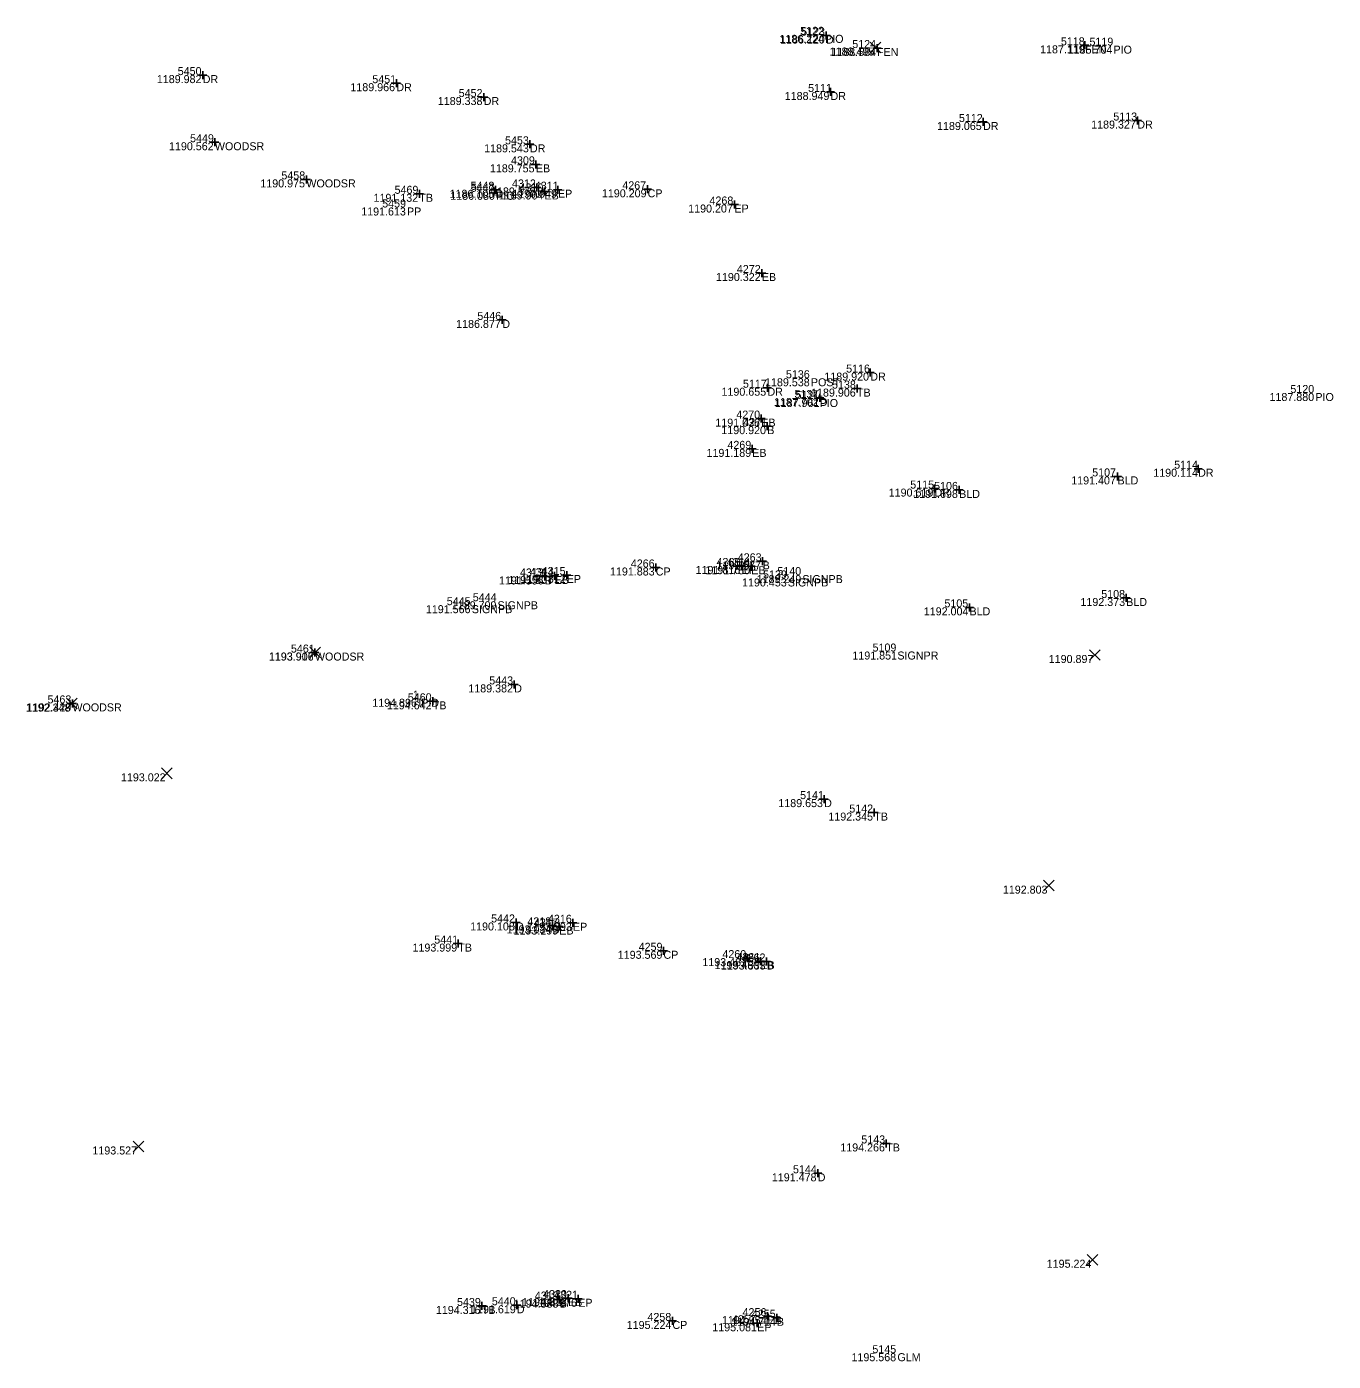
# Model space of a CAD drawing. Extents: x 2044997 to 2050342, y 455233 to 458054.
# Drawn here: x 2047538.1 to 2047701.3, y 457708.4 to 457875.1 of the extents above; entities that cross this region are included whole.
import ezdxf

# ---------------------------------------------------------------- set-up
doc = ezdxf.new("R2010")
doc.units = 0
for name, color, linetype in [('SV_X_Random_Point', 7, 'Continuous'), ('SV_X_Shot_Marker', 7, 'Continuous'), ('SV_X_Text_Comment', 7, 'Continuous'), ('SV_X_Text_Elevation', 7, 'Continuous'), ('SV_X_Text_Name', 7, 'Continuous')]:
    doc.layers.add(name, color=color, linetype=linetype)

msp = doc.modelspace()

# ---------------------------------------------------------------- linework, layer by layer
at = {"layer": 'SV_X_Random_Point'}
for p, q in [((2047643.48, 457871.84), (2047644.81, 457873.17)), ((2047643.48, 457873.17), (2047644.81, 457871.84)), ((2047573.45, 457796.27), (2047574.79, 457797.6)), ((2047573.45, 457797.6), (2047574.79, 457796.27)), ((2047670.88, 457795.95), (2047672.21, 457797.28)), ((2047670.88, 457797.28), (2047672.21, 457795.95)), ((2047543.06, 457789.89), (2047544.39, 457791.22)), ((2047543.06, 457791.22), (2047544.39, 457789.89)), ((2047554.93, 457781.16), (2047556.27, 457782.5)), ((2047554.93, 457782.5), (2047556.27, 457781.16)), ((2047665.1, 457767.13), (2047666.43, 457768.47)), ((2047665.1, 457768.47), (2047666.43, 457767.13)), ((2047551.41, 457734.54), (2047552.74, 457735.87)), ((2047551.41, 457735.87), (2047552.74, 457734.54)), ((2047670.56, 457720.39), (2047671.89, 457721.72)), ((2047670.56, 457721.72), (2047671.89, 457720.39))]:
    msp.add_line(p, q, dxfattribs=at)
at = {"layer": 'SV_X_Shot_Marker'}
for p, q in [((2047637.45, 457874.01), (2047638.45, 457874.01)), ((2047637.95, 457874.51), (2047637.95, 457873.51)), ((2047637.95, 457874.01), (2047637.95, 457874.01)), ((2047643.82, 457872.45), (2047644.82, 457872.45)), ((2047644.32, 457872.95), (2047644.32, 457871.95)), ((2047644.32, 457872.45), (2047644.32, 457872.45)), ((2047669.8, 457872.79), (2047670.8, 457872.79)), ((2047670.3, 457873.29), (2047670.3, 457872.29)), ((2047670.3, 457872.79), (2047670.3, 457872.79)), ((2047559.58, 457869.07), (2047560.58, 457869.07)), ((2047560.08, 457869.57), (2047560.08, 457868.57)), ((2047560.08, 457869.07), (2047560.08, 457869.07)), ((2047584.27, 457868.56), (2047584.27, 457867.56)), ((2047583.77, 457868.06), (2047584.77, 457868.06)), ((2047584.27, 457868.06), (2047584.27, 457868.06)), ((2047595.18, 457866.83), (2047595.18, 457865.83)), ((2047638.01, 457866.96), (2047639.01, 457866.96)), ((2047638.51, 457867.46), (2047638.51, 457866.46)), ((2047638.51, 457866.96), (2047638.51, 457866.96)), ((2047594.68, 457866.33), (2047595.68, 457866.33)), ((2047595.18, 457866.33), (2047595.18, 457866.33)), ((2047657.56, 457863.71), (2047657.56, 457862.71)), ((2047676.34, 457863.39), (2047677.34, 457863.39)), ((2047676.84, 457863.89), (2047676.84, 457862.89)), ((2047676.84, 457863.39), (2047676.84, 457863.39)), ((2047657.06, 457863.21), (2047658.06, 457863.21)), ((2047657.56, 457863.21), (2047657.56, 457863.21)), ((2047561.1, 457860.68), (2047562.1, 457860.68)), ((2047561.6, 457861.18), (2047561.6, 457860.18)), ((2047561.6, 457860.68), (2047561.6, 457860.68)), ((2047600.46, 457860.42), (2047601.46, 457860.42)), ((2047600.96, 457860.92), (2047600.96, 457859.92)), ((2047600.96, 457860.42), (2047600.96, 457860.42)), ((2047601.7, 457858.42), (2047601.7, 457857.42)), ((2047601.2, 457857.92), (2047602.2, 457857.92)), ((2047601.7, 457857.92), (2047601.7, 457857.92)), ((2047572.53, 457856.04), (2047573.53, 457856.04)), ((2047573.03, 457856.54), (2047573.03, 457855.54)), ((2047573.03, 457856.04), (2047573.03, 457856.04)), ((2047596.66, 457855.24), (2047596.66, 457854.24)), ((2047601.34, 457855.03), (2047602.34, 457855.03)), ((2047601.84, 457855.53), (2047601.84, 457854.53)), ((2047601.84, 457855.03), (2047601.84, 457855.03)), ((2047602.78, 457855.03), (2047602.78, 457854.03)), ((2047604.46, 457855.25), (2047604.46, 457854.25)), ((2047615.66, 457855.3), (2047615.66, 457854.3)), ((2047586.65, 457854.24), (2047587.65, 457854.24)), ((2047587.15, 457854.74), (2047587.15, 457853.74)), ((2047587.15, 457854.24), (2047587.15, 457854.24)), ((2047596.16, 457854.74), (2047597.16, 457854.74)), ((2047596.66, 457854.74), (2047596.66, 457854.74)), ((2047602.28, 457854.53), (2047603.28, 457854.53)), ((2047602.78, 457854.53), (2047602.78, 457854.53)), ((2047603.96, 457854.75), (2047604.96, 457854.75)), ((2047604.46, 457854.75), (2047604.46, 457854.75)), ((2047615.16, 457854.8), (2047616.16, 457854.8)), ((2047615.66, 457854.8), (2047615.66, 457854.8)), ((2047626.51, 457853.4), (2047626.51, 457852.4)), ((2047626.01, 457852.9), (2047627.01, 457852.9)), ((2047626.51, 457852.9), (2047626.51, 457852.9)), ((2047629.43, 457844.34), (2047630.43, 457844.34)), ((2047629.93, 457844.84), (2047629.93, 457843.84)), ((2047629.93, 457844.34), (2047629.93, 457844.34)), ((2047597.01, 457838.48), (2047598.01, 457838.48)), ((2047597.51, 457838.98), (2047597.51, 457837.98)), ((2047597.51, 457838.48), (2047597.51, 457838.48)), ((2047642.98, 457831.9), (2047643.98, 457831.9)), ((2047643.48, 457832.4), (2047643.48, 457831.4)), ((2047643.48, 457831.9), (2047643.48, 457831.9)), ((2047630.13, 457830.01), (2047631.13, 457830.01)), ((2047630.63, 457830.51), (2047630.63, 457829.51)), ((2047630.63, 457830.01), (2047630.63, 457830.01)), ((2047641.82, 457830.4), (2047641.82, 457829.4)), ((2047636.67, 457828.73), (2047637.67, 457828.73)), ((2047637.17, 457829.23), (2047637.17, 457828.23)), ((2047637.17, 457828.73), (2047637.17, 457828.73)), ((2047641.32, 457829.9), (2047642.32, 457829.9)), ((2047641.82, 457829.9), (2047641.82, 457829.9)), ((2047629.86, 457826.65), (2047629.86, 457825.65)), ((2047629.36, 457826.15), (2047630.36, 457826.15)), ((2047629.86, 457826.15), (2047629.86, 457826.15)), ((2047630.11, 457825.21), (2047631.11, 457825.21)), ((2047630.61, 457825.71), (2047630.61, 457824.71)), ((2047630.61, 457825.21), (2047630.61, 457825.21)), ((2047628.23, 457822.37), (2047629.23, 457822.37)), ((2047628.73, 457822.87), (2047628.73, 457821.87)), ((2047628.73, 457822.37), (2047628.73, 457822.37)), ((2047684.43, 457820.39), (2047684.43, 457819.39)), ((2047673.86, 457818.93), (2047674.86, 457818.93)), ((2047674.36, 457819.43), (2047674.36, 457818.43)), ((2047674.36, 457818.93), (2047674.36, 457818.93)), ((2047683.93, 457819.89), (2047684.93, 457819.89)), ((2047684.43, 457819.89), (2047684.43, 457819.89)), ((2047650.99, 457817.41), (2047651.99, 457817.41)), ((2047651.49, 457817.91), (2047651.49, 457816.91)), ((2047651.49, 457817.41), (2047651.49, 457817.41)), ((2047654.08, 457817.24), (2047655.08, 457817.24)), ((2047654.58, 457817.74), (2047654.58, 457816.74)), ((2047654.58, 457817.24), (2047654.58, 457817.24)), ((2047629.53, 457808.32), (2047630.53, 457808.32)), ((2047630.03, 457808.82), (2047630.03, 457807.82)), ((2047630.03, 457808.32), (2047630.03, 457808.32)), ((2047602.82, 457806.93), (2047602.82, 457805.93)), ((2047604.04, 457806.99), (2047604.04, 457805.99)), ((2047605.56, 457807.11), (2047605.56, 457806.11)), ((2047616.18, 457807.55), (2047617.18, 457807.55)), ((2047616.68, 457808.05), (2047616.68, 457807.05)), ((2047616.68, 457807.55), (2047616.68, 457807.55)), ((2047626.9, 457807.74), (2047627.9, 457807.74)), ((2047627.4, 457808.24), (2047627.4, 457807.24)), ((2047627.4, 457807.74), (2047627.4, 457807.74)), ((2047628.11, 457807.71), (2047629.11, 457807.71)), ((2047628.61, 457808.21), (2047628.61, 457807.21)), ((2047628.61, 457807.71), (2047628.61, 457807.71)), ((2047602.32, 457806.43), (2047603.32, 457806.43)), ((2047602.82, 457806.43), (2047602.82, 457806.43)), ((2047603.54, 457806.49), (2047604.54, 457806.49)), ((2047604.04, 457806.49), (2047604.04, 457806.49)), ((2047605.06, 457806.61), (2047606.06, 457806.61)), ((2047605.56, 457806.61), (2047605.56, 457806.61)), ((2047674.95, 457803.74), (2047675.95, 457803.74)), ((2047675.45, 457804.24), (2047675.45, 457803.24)), ((2047675.45, 457803.74), (2047675.45, 457803.74)), ((2047655.37, 457802.57), (2047656.37, 457802.57)), ((2047655.87, 457803.07), (2047655.87, 457802.07)), ((2047655.87, 457802.57), (2047655.87, 457802.57)), ((2047573.6, 457796.92), (2047574.6, 457796.92)), ((2047574.1, 457797.42), (2047574.1, 457796.42)), ((2047574.1, 457796.92), (2047574.1, 457796.92)), ((2047598.99, 457793.44), (2047598.99, 457792.44)), ((2047598.49, 457792.94), (2047599.49, 457792.94)), ((2047598.99, 457792.94), (2047598.99, 457792.94)), ((2047543.3, 457790.57), (2047544.3, 457790.57)), ((2047543.8, 457791.07), (2047543.8, 457790.07)), ((2047543.8, 457790.57), (2047543.8, 457790.57)), ((2047588.32, 457790.83), (2047589.32, 457790.83)), ((2047588.82, 457791.33), (2047588.82, 457790.33)), ((2047588.82, 457790.83), (2047588.82, 457790.83)), ((2047637.21, 457778.61), (2047638.21, 457778.61)), ((2047637.71, 457779.11), (2047637.71, 457778.11)), ((2047637.71, 457778.61), (2047637.71, 457778.61)), ((2047643.48, 457776.93), (2047644.48, 457776.93)), ((2047643.98, 457777.43), (2047643.98, 457776.43)), ((2047643.98, 457776.93), (2047643.98, 457776.93)), ((2047599.22, 457763.7), (2047599.22, 457762.7)), ((2047603.76, 457763.33), (2047603.76, 457762.33)), ((2047606.33, 457763.66), (2047606.33, 457762.66)), ((2047598.72, 457763.2), (2047599.72, 457763.2)), ((2047599.22, 457763.2), (2047599.22, 457763.2)), ((2047603.26, 457762.83), (2047604.26, 457762.83)), ((2047603.76, 457762.83), (2047603.76, 457762.83)), ((2047604.12, 457762.69), (2047605.12, 457762.69)), ((2047604.62, 457763.19), (2047604.62, 457762.19)), ((2047604.62, 457762.69), (2047604.62, 457762.69)), ((2047605.83, 457763.16), (2047606.83, 457763.16)), ((2047606.33, 457763.16), (2047606.33, 457763.16)), ((2047591.51, 457760.56), (2047592.51, 457760.56)), ((2047592.01, 457761.06), (2047592.01, 457760.06)), ((2047592.01, 457760.56), (2047592.01, 457760.56)), ((2047617.64, 457760.16), (2047617.64, 457759.16)), ((2047617.14, 457759.66), (2047618.14, 457759.66)), ((2047617.64, 457759.66), (2047617.64, 457759.66)), ((2047627.62, 457758.74), (2047628.62, 457758.74)), ((2047628.12, 457759.24), (2047628.12, 457758.24)), ((2047628.12, 457758.74), (2047628.12, 457758.74)), ((2047629.25, 457758.37), (2047630.25, 457758.37)), ((2047629.75, 457758.87), (2047629.75, 457757.87)), ((2047629.75, 457758.37), (2047629.75, 457758.37)), ((2047630.03, 457758.32), (2047631.03, 457758.32)), ((2047630.53, 457758.82), (2047630.53, 457757.82)), ((2047630.53, 457758.32), (2047630.53, 457758.32)), ((2047644.97, 457735.59), (2047645.97, 457735.59)), ((2047645.47, 457736.09), (2047645.47, 457735.09)), ((2047645.47, 457735.59), (2047645.47, 457735.59)), ((2047636.41, 457731.86), (2047637.41, 457731.86)), ((2047636.91, 457732.36), (2047636.91, 457731.36)), ((2047636.91, 457731.86), (2047636.91, 457731.86)), ((2047604.67, 457716.58), (2047604.67, 457715.58)), ((2047605.72, 457716.77), (2047605.72, 457715.77)), ((2047606.99, 457716.68), (2047606.99, 457715.68)), ((2047594.45, 457715.28), (2047595.45, 457715.28)), ((2047594.95, 457715.78), (2047594.95, 457714.78)), ((2047594.95, 457715.28), (2047594.95, 457715.28)), ((2047598.82, 457715.37), (2047599.82, 457715.37)), ((2047599.32, 457715.87), (2047599.32, 457714.87)), ((2047599.32, 457715.37), (2047599.32, 457715.37)), ((2047604.17, 457716.08), (2047605.17, 457716.08)), ((2047604.67, 457716.08), (2047604.67, 457716.08)), ((2047605.22, 457716.27), (2047606.22, 457716.27)), ((2047605.72, 457716.27), (2047605.72, 457716.27)), ((2047606.49, 457716.18), (2047607.49, 457716.18)), ((2047606.99, 457716.18), (2047606.99, 457716.18)), ((2047618.26, 457713.41), (2047619.26, 457713.41)), ((2047618.76, 457713.91), (2047618.76, 457712.91)), ((2047618.76, 457713.41), (2047618.76, 457713.41)), ((2047629.35, 457713.62), (2047629.35, 457712.62)), ((2047630.15, 457714.01), (2047631.15, 457714.01)), ((2047630.65, 457714.51), (2047630.65, 457713.51)), ((2047630.65, 457714.01), (2047630.65, 457714.01)), ((2047631.31, 457713.81), (2047632.31, 457713.81)), ((2047631.81, 457714.31), (2047631.81, 457713.31)), ((2047631.81, 457713.81), (2047631.81, 457713.81)), ((2047628.85, 457713.12), (2047629.85, 457713.12)), ((2047629.35, 457713.12), (2047629.35, 457713.12))]:
    msp.add_line(p, q, dxfattribs=at)

# ---------------------------------------------------------------- texts
at = {"layer": 'SV_X_Text_Comment'}
for s, p in [('PIO', (2047637.83, 457873.1)), ('D', (2047637.95, 457873.01)), ('FEN', (2047644.32, 457871.45)), ('FEN', (2047670.3, 457871.79)), ('PIO', (2047673.86, 457871.75)), ('DR', (2047560.08, 457868.07)), ('DR', (2047584.27, 457867.06)), ('DR', (2047638.51, 457865.96)), ('DR', (2047595.18, 457865.33)), ('DR', (2047676.84, 457862.39)), ('DR', (2047657.56, 457862.21)), ('WOODSR', (2047561.6, 457859.68)), ('DR', (2047600.96, 457859.42)), ('EB', (2047601.7, 457856.92)), ('WOODSR', (2047573.03, 457855.04)), ('B', (2047601.84, 457854.03)), ('TB', (2047587.15, 457853.24)), ('D', (2047596.66, 457853.74)), ('PIO', (2047596.73, 457853.49)), ('EB', (2047602.78, 457853.53)), ('EP', (2047604.46, 457853.75)), ('CP', (2047615.66, 457853.8)), ('PP', (2047585.6, 457851.53)), ('EP', (2047626.51, 457851.9)), ('EB', (2047629.93, 457843.34)), ('D', (2047597.51, 457837.48)), ('DR', (2047643.48, 457830.9)), ('DR', (2047630.63, 457829.01)), ('POST', (2047636.06, 457830.19)), ('PIO', (2047637.15, 457827.6)), ('D', (2047637.17, 457827.73)), ('TB', (2047641.82, 457828.9)), ('PIO', (2047699.08, 457828.35)), ('EB', (2047629.86, 457825.15)), ('B', (2047630.61, 457824.21)), ('EB', (2047628.73, 457821.37)), ('BLD', (2047674.36, 457817.93)), ('DR', (2047684.43, 457818.89)), ('DR', (2047651.49, 457816.41)), ('BLD', (2047654.58, 457816.24)), ('B', (2047630.03, 457807.32)), ('CP', (2047616.68, 457806.55)), ('EP', (2047627.4, 457806.74)), ('EB', (2047628.61, 457806.71)), ('SIGNPB', (2047634.99, 457805.6)), ('B', (2047602.82, 457805.43)), ('EB', (2047604.04, 457805.49)), ('EP', (2047605.56, 457805.61)), ('SIGNPB', (2047633.18, 457805.18)), ('SIGNPB', (2047596.91, 457802.33)), ('BLD', (2047675.45, 457802.74)), ('SIGNPB', (2047593.7, 457801.84)), ('BLD', (2047655.87, 457801.57)), ('WOODSR', (2047574.1, 457795.92)), ('SIGNPR', (2047646.86, 457796.05)), ('D', (2047598.99, 457791.94)), ('WOODSR', (2047543.8, 457789.57)), ('IPID', (2047587, 457790.15)), ('TB', (2047588.82, 457789.83)), ('D', (2047637.71, 457777.61)), ('TB', (2047643.98, 457775.93)), ('D', (2047599.22, 457762.2)), ('B', (2047603.76, 457761.83)), ('EB', (2047604.62, 457761.69)), ('EP', (2047606.33, 457762.16)), ('TB', (2047592.01, 457759.56)), ('CP', (2047617.64, 457758.66)), ('EP', (2047628.12, 457757.74)), ('EB', (2047629.75, 457757.37)), ('B', (2047630.53, 457757.32)), ('TB', (2047645.47, 457734.59)), ('D', (2047636.91, 457730.86)), ('TB', (2047594.95, 457714.28)), ('D', (2047599.32, 457714.37)), ('B', (2047604.67, 457715.08)), ('EB', (2047605.72, 457715.27)), ('EP', (2047606.99, 457715.18)), ('CP', (2047618.76, 457712.41)), ('EB', (2047630.65, 457713.01)), ('B', (2047631.81, 457712.81)), ('EP', (2047629.35, 457712.12)), ('GLM', (2047646.87, 457708.38))]:
    msp.add_text(s, height=1, dxfattribs=at).set_placement(p)
at = {"layer": 'SV_X_Text_Elevation'}
for s, p in [('1186.224', (2047632.13, 457873.1)), ('1186.120', (2047632.21, 457873.01)), ('1188.495', (2047638.4, 457871.51)), ('1188.584', (2047638.61, 457871.45)), ('1187.119', (2047664.69, 457871.79)), ('1185.704', (2047668.15, 457871.75)), ('1189.982', (2047554.35, 457868.07)), ('1189.966', (2047578.53, 457867.06)), ('1188.949', (2047632.79, 457865.96)), ('1189.338', (2047589.45, 457865.33)), ('1189.327', (2047671.07, 457862.39)), ('1189.065', (2047651.82, 457862.21)), ('1190.562', (2047555.87, 457859.68)), ('1189.543', (2047595.24, 457859.42)), ('1189.755', (2047595.96, 457856.92)), ('1190.975', (2047567.28, 457855.04)), ('1189.578', (2047596.1, 457854.03)), ('1191.132', (2047581.42, 457853.24)), ('1186.105', (2047590.92, 457853.74)), ('1186.080', (2047591, 457853.49)), ('1189.904', (2047597.07, 457853.53)), ('1190.049', (2047598.75, 457853.75)), ('1190.209', (2047609.95, 457853.8)), ('1191.613', (2047579.88, 457851.53)), ('1190.207', (2047620.73, 457851.9)), ('1190.322', (2047624.2, 457843.34)), ('1186.877', (2047591.74, 457837.48)), ('1189.920', (2047637.74, 457830.9)), ('1190.655', (2047624.89, 457829.01)), ('1189.538', (2047630.33, 457830.19)), ('1187.702', (2047631.45, 457827.73)), ('1187.961', (2047631.54, 457827.6)), ('1189.906', (2047636.08, 457828.9)), ('1187.880', (2047693.35, 457828.35)), ('1191.036', (2047624.12, 457825.15)), ('1190.920', (2047624.87, 457824.21)), ('1191.189', (2047623.02, 457821.37)), ('1191.407', (2047668.58, 457817.93)), ('1190.114', (2047678.83, 457818.89)), ('1190.619', (2047645.78, 457816.41)), ('1191.698', (2047648.84, 457816.24)), ('1191.577', (2047624.25, 457807.32)), ('1191.812', (2047599.84, 457805.61)), ('1191.883', (2047610.96, 457806.55)), ('1191.816', (2047621.66, 457806.74)), ('1191.780', (2047622.88, 457806.71)), ('1189.249', (2047629.28, 457805.6)), ('1191.556', (2047597.09, 457805.43)), ('1191.807', (2047598.26, 457805.49)), ('1190.453', (2047627.46, 457805.18)), ('1189.709', (2047591.2, 457802.33)), ('1192.373', (2047669.73, 457802.74)), ('1191.566', (2047587.96, 457801.84)), ('1192.004', (2047650.16, 457801.57)), ('1193.917', (2047568.34, 457795.93)), ('1193.906', (2047568.36, 457795.92)), ('1191.851', (2047641.24, 457796.05)), ('1190.897', (2047665.77, 457795.62)), ('1189.382', (2047593.26, 457791.94)), ('1192.348', (2047537.99, 457789.55)), ('1192.429', (2047538.09, 457789.57)), ('1194.896', (2047581.26, 457790.15)), ('1194.642', (2047583.09, 457789.83)), ('1193.022', (2047549.87, 457780.83)), ('1189.653', (2047631.99, 457777.61)), ('1192.345', (2047638.24, 457775.93)), ('1192.803', (2047660.04, 457766.8)), ('1190.108', (2047593.49, 457762.2)), ('1193.034', (2047598.05, 457761.83)), ('1193.299', (2047598.91, 457761.69)), ('1193.393', (2047600.61, 457762.16)), ('1193.999', (2047586.29, 457759.56)), ('1193.569', (2047611.93, 457758.66)), ('1193.481', (2047622.5, 457757.74)), ('1193.460', (2047624.02, 457757.37)), ('1193.333', (2047624.81, 457757.32)), ('1193.527', (2047546.3, 457734.21)), ('1194.266', (2047639.73, 457734.59)), ('1191.478', (2047631.18, 457730.86)), ('1195.224', (2047665.52, 457720.06)), ('1194.316', (2047589.21, 457714.28)), ('1191.619', (2047593.61, 457714.37)), ('1194.588', (2047598.94, 457715.08)), ('1194.818', (2047599.98, 457715.27)), ('1194.876', (2047601.25, 457715.18)), ('1195.224', (2047613.05, 457712.41)), ('1194.954', (2047624.94, 457713.01)), ('1194.714', (2047626.11, 457712.81)), ('1195.081', (2047623.74, 457712.12)), ('1195.568', (2047641.13, 457708.38))]:
    msp.add_text(s, height=1, dxfattribs=at).set_placement(p)
at = {"layer": 'SV_X_Text_Name'}
for s, p in [('5122', (2047634.72, 457874.1)), ('5123', (2047634.84, 457874.01)), ('5124', (2047641.23, 457872.45)), ('5118', (2047667.29, 457872.79)), ('5119', (2047670.86, 457872.75)), ('5450', (2047556.96, 457869.07)), ('5451', (2047581.27, 457868.06)), ('5452', (2047592.06, 457866.33)), ('5111', (2047635.71, 457866.96)), ('5112', (2047654.55, 457863.21)), ('5113', (2047673.84, 457863.39)), ('5449', (2047558.5, 457860.68)), ('5453', (2047597.85, 457860.42)), ('4309', (2047598.6, 457857.92)), ('5458', (2047569.91, 457856.04)), ('5469', (2047584.05, 457854.24)), ('5448', (2047593.54, 457854.74)), ('5447', (2047593.57, 457854.49)), ('4312', (2047598.72, 457855.03)), ('4310', (2047599.66, 457854.53)), ('4311', (2047601.57, 457854.75)), ('4267', (2047612.5, 457854.8)), ('5459', (2047582.5, 457852.53)), ('4268', (2047623.39, 457852.9)), ('4272', (2047626.81, 457844.34)), ('5446', (2047594.39, 457838.48)), ('5136', (2047632.94, 457831.19)), ('5116', (2047640.46, 457831.9)), ('5117', (2047627.57, 457830.01)), ('5138', (2047638.7, 457829.9)), ('5120', (2047695.96, 457829.35)), ('5137', (2047634.01, 457828.73)), ('5121', (2047634.15, 457828.6)), ('4270', (2047626.74, 457826.15)), ('4271', (2047627.61, 457825.21)), ('4269', (2047625.63, 457822.37)), ('5114', (2047681.44, 457819.89)), ('5115', (2047648.47, 457817.41)), ('5107', (2047671.2, 457818.93)), ('5106', (2047651.45, 457817.24)), ('4266', (2047613.56, 457807.55)), ('4265', (2047624.27, 457807.74)), ('4264', (2047625.52, 457807.71)), ('4263', (2047626.92, 457808.32)), ('4313', (2047599.71, 457806.43)), ('4314', (2047600.95, 457806.49)), ('4315', (2047602.43, 457806.61)), ('5139', (2047630.08, 457806.18)), ('5140', (2047631.87, 457806.6)), ('5445', (2047590.57, 457802.84)), ('5444', (2047593.82, 457803.33)), ('5105', (2047652.74, 457802.57)), ('5108', (2047672.33, 457803.74)), ('5461', (2047571.1, 457796.92)), ('5109', (2047643.76, 457797.05)), ('5443', (2047595.88, 457792.94)), ('5460', (2047585.7, 457790.83)), ('1', (2047586.33, 457791.15)), ('5463', (2047540.69, 457790.57)), ('5141', (2047634.71, 457778.61)), ('5142', (2047640.86, 457776.93)), ('5442', (2047596.11, 457763.2)), ('4318', (2047600.64, 457762.83)), ('4317', (2047601.46, 457762.69)), ('4316', (2047603.21, 457763.16)), ('5441', (2047589.01, 457760.56)), ('4259', (2047614.54, 457759.66)), ('4260', (2047625, 457758.74)), ('4261', (2047626.75, 457758.37)), ('4262', (2047627.41, 457758.32)), ('5143', (2047642.36, 457735.59)), ('5144', (2047633.82, 457731.86)), ('4319', (2047601.57, 457716.08)), ('4320', (2047602.6, 457716.27)), ('4321', (2047603.99, 457716.18)), ('5439', (2047591.85, 457715.28)), ('5440', (2047596.2, 457715.37)), ('4256', (2047627.52, 457714.01)), ('4258', (2047615.64, 457713.41)), ('4257', (2047626.19, 457713.12)), ('4255', (2047628.68, 457713.81)), ('5145', (2047643.74, 457709.38))]:
    msp.add_text(s, height=1, dxfattribs=at).set_placement(p)

doc.saveas('drawing.dxf')
